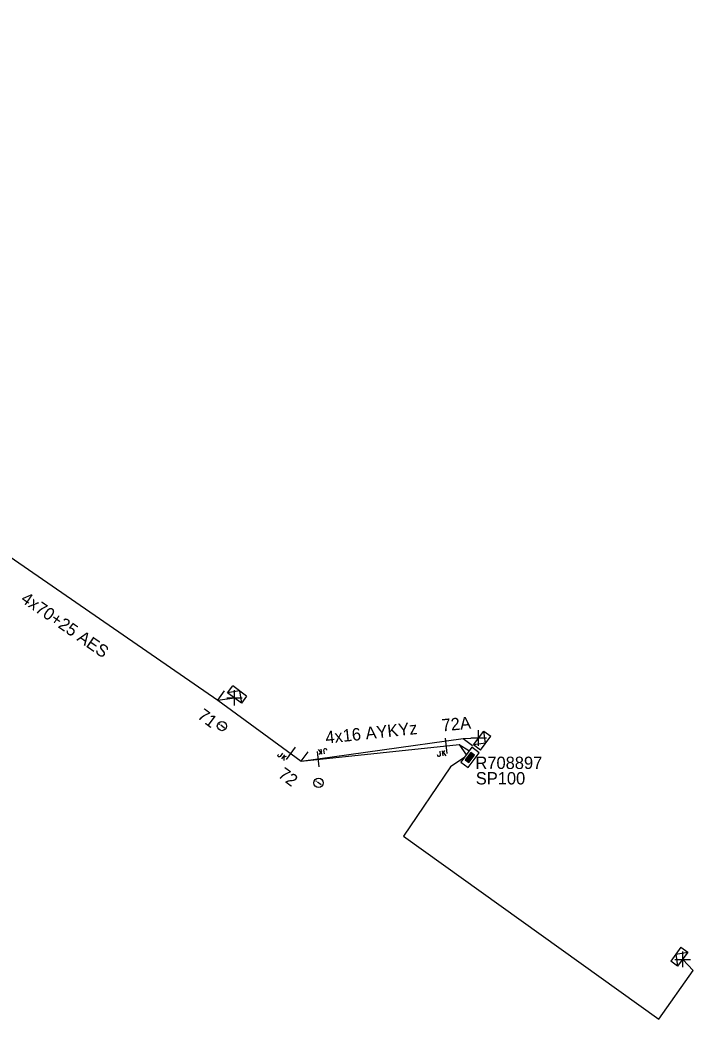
# Model space of a CAD drawing. Extents: x -540247 to -537390, y -1183887 to -1180355.
# Drawn here: x -537607.2 to -537552.5, y -1180619.3 to -1180538.2 of the extents above; entities that cross this region are included whole.
import ezdxf

# ---------------------------------------------------------------- set-up
doc = ezdxf.new("R2010")
doc.units = 0
for name, color, linetype in [('Vrstva 1', 7, 'Continuous'), ('Vrstva 10', 7, 'Continuous'), ('Vrstva 13', 7, 'Continuous'), ('Vrstva 14', 7, 'Continuous'), ('Vrstva 15', 7, 'Continuous'), ('Vrstva 18', 7, 'Continuous'), ('Vrstva 2', 7, 'Continuous'), ('Vrstva 28', 7, 'Continuous'), ('Vrstva 29', 7, 'Continuous'), ('Vrstva 30', 7, 'Continuous'), ('Vrstva 31', 7, 'Continuous'), ('Vrstva 34', 7, 'Continuous'), ('Vrstva 36', 7, 'Continuous'), ('Vrstva 50', 7, 'Continuous'), ('Vrstva 51', 7, 'Continuous'), ('Vrstva 52', 7, 'Continuous'), ('Vrstva 53', 7, 'Continuous'), ('Vrstva 54', 7, 'Continuous'), ('Vrstva 8', 7, 'Continuous'), ('Vrstva 9', 7, 'Continuous')]:
    doc.layers.add(name, color=color, linetype=linetype)

# ---------------------------------------------------------------- blocks, each defined once
blk = doc.blocks.new('NN840')
at = {"layer": 'Vrstva 15'}
for points in [[(0.003, 0.619), (0.003, -0.631)], [(-0.745, -0.71), (-0.745, -0.66)], [(-0.73, -0.764), (-0.745, -0.71)], [(-0.657, -0.798), (-0.73, -0.764)], [(-0.627, -0.798), (-0.657, -0.798)], [(-0.558, -0.764), (-0.627, -0.798)], [(-0.538, -0.71), (-0.558, -0.764)], [(-0.538, -0.385), (-0.538, -0.71)], [(-0.332, -0.385), (-0.332, -0.798)], [(-0.332, -0.641), (-0.125, -0.385)], [(-0.263, -0.557), (-0.091, -0.798)]]:
    blk.add_lwpolyline(points, dxfattribs=at)
blk = doc.blocks.new('NN770')
at = {"layer": 'Vrstva 10'}
for p, q in [((0.002, 0.187), (0.002, 0.263)), ((0.002, -0.276), (0.002, 0.111))]:
    blk.add_line(p, q, dxfattribs=at)
blk.add_circle((0, -0.008), 0.375, dxfattribs=at)
blk = doc.blocks.new('NN800')
at = {"layer": 'Vrstva 1'}
for points in [[(-0.442, 0.442), (0.442, -0.442)], [(-0.442, -0.442), (0.442, 0.442)]]:
    blk.add_lwpolyline(points, dxfattribs=at)
blk = doc.blocks.new('NN620')
at = {"layer": 'Vrstva 8'}
for points in [[(0.752, 0.004), (-0.748, 0.004)], [(-0.748, 0.004), (-0.748, -0.746)], [(0.752, -0.746), (0.752, 0.004)], [(-0.748, -0.746), (0.752, -0.746)], [(0.368, -0.18), (-0.376, -0.18)], [(-0.376, -0.18), (-0.376, -0.558)], [(-0.376, -0.558), (0.368, -0.558)], [(0.321, -0.227), (-0.329, -0.227)], [(-0.329, -0.227), (-0.329, -0.51)], [(-0.329, -0.51), (0.321, -0.51)], [(0.274, -0.274), (-0.281, -0.274)], [(-0.281, -0.274), (-0.281, -0.463)], [(-0.281, -0.463), (0.274, -0.463)], [(0.227, -0.321), (-0.234, -0.321)], [(-0.234, -0.321), (-0.234, -0.416)], [(-0.234, -0.416), (0.227, -0.416)], [(-0.193, -0.369), (0.185, -0.369)], [(0.227, -0.416), (0.227, -0.321)], [(0.274, -0.463), (0.274, -0.274)], [(0.321, -0.51), (0.321, -0.227)], [(0.368, -0.558), (0.368, -0.18)]]:
    blk.add_lwpolyline(points, dxfattribs=at)
blk = doc.blocks.new('NN630')
at = {"layer": 'Vrstva 9'}
for points in [[(-0.003, -0.7), (-0.703, 0)], [(-0.703, -0.7), (-0.703, 0), (0.697, 0), (0.697, -0.7)], [(-0.703, -0.7), (0.697, -0.7)], [(-0.003, -0.7), (0.697, 0)]]:
    blk.add_lwpolyline(points, dxfattribs=at)
blk = doc.blocks.new('NN510')
at = {"layer": 'Vrstva 2'}
blk.add_lwpolyline([(0.001, 0.002), (0.001, 0.939)], dxfattribs=at)

msp = doc.modelspace()

# ---------------------------------------------------------------- linework, layer by layer
at = {"layer": 'Vrstva 50'}
msp.add_lwpolyline([(-537694.26, -1180538.199), (-537691.624, -1180539.786), (-537675.507, -1180549.486), (-537663.756, -1180552.682), (-537651.753, -1180559.088), (-537616.15, -1180576.16), (-537591.135, -1180593.384), (-537584.357, -1180598.332)], dxfattribs=at)
at = {"layer": 'Vrstva 52'}
for points in [[(-537584.357, -1180598.332), (-537571.532, -1180596.979), (-537570.96, -1180597.819)], [(-537571.075, -1180598.015), (-537572.231, -1180598.804), (-537576.04, -1180604.433), (-537555.316, -1180619.264), (-537552.54, -1180615.33), (-537553.38, -1180614.422)]]:
    msp.add_lwpolyline(points, dxfattribs=at)
at = {"layer": 'Vrstva 54'}
for points in [[(-537591.135, -1180593.384), (-537589.777, -1180593.207)], [(-537584.357, -1180598.332), (-537571.199, -1180596.51), (-537569.949, -1180596.46)]]:
    msp.add_lwpolyline(points, dxfattribs=at)

# ---------------------------------------------------------------- block references
at = {"layer": 'Vrstva 13'}
for p, rotation in [((-537591.135, -1180593.384), -36.332614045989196), ((-537571.532, -1180596.979), -122.1310999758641), ((-537571.199, -1180596.509), -126.67042216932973), ((-537584.357, -1180598.332), -36.33261389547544)]:
    msp.add_blockref('NN510', p, dxfattribs=dict(at, rotation=rotation))
at = {"layer": 'Vrstva 18'}
for p, rotation in [((-537585.219, -1180597.703), -36.129774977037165), ((-537572.611, -1180597.093), 6.022261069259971), ((-537582.976, -1180598.186), -173.97773879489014)]:
    msp.add_blockref('NN840', p, dxfattribs=dict(at, rotation=rotation))
at = {"layer": 'Vrstva 28', "rotation": 53.32957783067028}
msp.add_blockref('NN620', (-537570.96, -1180597.819), dxfattribs=at)
at = {"layer": 'Vrstva 31'}
for p, rotation in [((-537589.777, -1180593.207), 143.66738606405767), ((-537569.949, -1180596.46), 53.32957783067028), ((-537553.38, -1180614.422), -125.94396681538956)]:
    msp.add_blockref('NN630', p, dxfattribs=dict(at, rotation=rotation))
at = {"layer": 'Vrstva 34', "rotation": 45}
for p in [(-537589.777, -1180593.207), (-537569.949, -1180596.46), (-537553.38, -1180614.422)]:
    msp.add_blockref('NN800', p, dxfattribs=at)
at = {"layer": 'Vrstva 36', "rotation": 53.68041948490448}
for p in [(-537590.804, -1180595.488), (-537582.959, -1180600.101)]:
    msp.add_blockref('NN770', p, dxfattribs=at)

# ---------------------------------------------------------------- texts
at = {"layer": 'Vrstva 14'}
for s, rotation, p in [('71', 323.196, (-537592.863, -1180594.8)), ('72A', 5.575, (-537572.907, -1180595.933)), ('72', 323.328, (-537586.318, -1180599.574))]:
    msp.add_text(s, height=1, rotation=rotation, dxfattribs=at).set_placement(p)
at = {"layer": 'Vrstva 29'}
msp.add_text('R708897', height=1, dxfattribs=at).set_placement((-537570.211, -1180598.975))
at = {"layer": 'Vrstva 30'}
msp.add_text('SP100', height=1, dxfattribs=at).set_placement((-537570.184, -1180600.23))
at = {"layer": 'Vrstva 51'}
msp.add_text('4x70+25 AES', height=1, rotation=325.451, dxfattribs=at).set_placement((-537607.205, -1180585.358))
at = {"layer": 'Vrstva 53'}
msp.add_text('4x16 AYKYz', height=1, rotation=6.022, dxfattribs=at).set_placement((-537582.343, -1180596.923))

doc.saveas('drawing.dxf')
